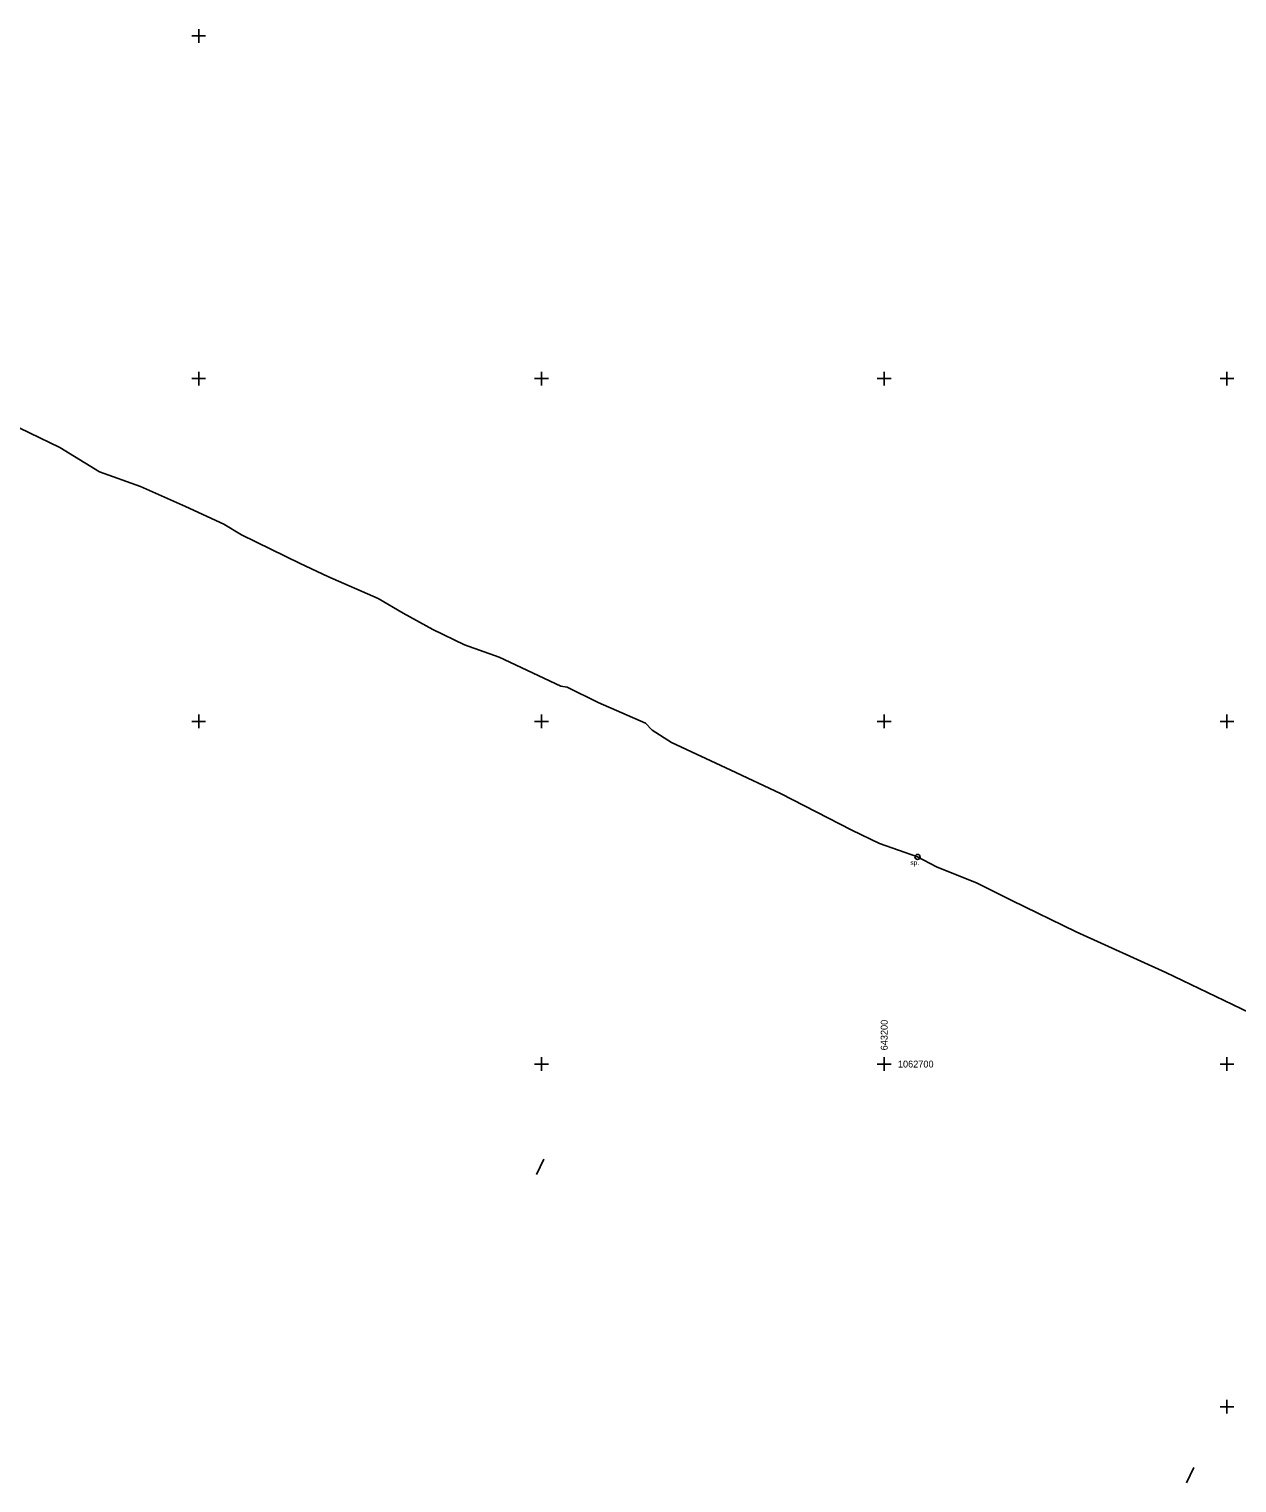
# Model space of a CAD drawing. Extents: x -643802 to -640936, y -1063811 to -1062198.
# Drawn here: x -643449.5 to -643097.1, y -1062822.2 to -1062398 of the extents above; entities that cross this region are included whole.
import ezdxf

# ---------------------------------------------------------------- set-up
doc = ezdxf.new("R2010")
doc.units = 0
for name, color, linetype in [('Vrstva 60', 7, 'Continuous'), ('Vrstva 8', 7, 'Continuous'), ('Vrstva 9', 7, 'Continuous')]:
    doc.layers.add(name, color=color, linetype=linetype)

msp = doc.modelspace()

# ---------------------------------------------------------------- linework, layer by layer
at = {"layer": 'Vrstva 60'}
for points in [[(-643398, -1062400), (-643402, -1062400)], [(-643400, -1062398), (-643400, -1062402)], [(-643400, -1062498), (-643400, -1062502)], [(-643300, -1062498), (-643300, -1062502)], [(-643200, -1062498), (-643200, -1062502)], [(-643100, -1062498), (-643100, -1062502)], [(-643398, -1062500), (-643402, -1062500)], [(-643298, -1062500), (-643302, -1062500)], [(-643198, -1062500), (-643202, -1062500)], [(-643098, -1062500), (-643102, -1062500)], [(-643398, -1062600), (-643402, -1062600)], [(-643400, -1062598), (-643400, -1062602)], [(-643298, -1062600), (-643302, -1062600)], [(-643300, -1062598), (-643300, -1062602)], [(-643198, -1062600), (-643202, -1062600)], [(-643200, -1062598), (-643200, -1062602)], [(-643098, -1062600), (-643102, -1062600)], [(-643100, -1062598), (-643100, -1062602)], [(-643298, -1062700), (-643302, -1062700)], [(-643300, -1062698), (-643300, -1062702)], [(-643198, -1062700), (-643202, -1062700)], [(-643200, -1062698), (-643200, -1062702)], [(-643098, -1062700), (-643102, -1062700)], [(-643100, -1062698), (-643100, -1062702)], [(-643301.484, -1062732.21), (-643299.366, -1062727.745)], [(-643100, -1062798), (-643100, -1062802)], [(-643098, -1062800), (-643102, -1062800)], [(-643111.748, -1062822.212), (-643109.63, -1062817.747)]]:
    msp.add_lwpolyline(points, dxfattribs=at)
at = {"layer": 'Vrstva 8'}
msp.add_lwpolyline([(-643467.19, -1062507.22), (-643440.51, -1062520.07), (-643428.95, -1062527.23), (-643417, -1062531.48), (-643403.89, -1062537.31), (-643392.67, -1062542.44), (-643387.58, -1062545.57), (-643370.39, -1062553.92), (-643362.37, -1062557.69), (-643347.63, -1062564.19), (-643340.35, -1062568.39), (-643331.75, -1062573.17), (-643322.48, -1062577.71), (-643312.32, -1062581.29), (-643294.34, -1062589.7), (-643292.5, -1062589.99), (-643283.44, -1062594.47), (-643269.69, -1062600.53), (-643267.69, -1062602.55), (-643262.1, -1062606.13), (-643244.77, -1062614.28), (-643230.28, -1062621.06), (-643209.47, -1062631.73), (-643201.41, -1062635.63), (-643190.27, -1062639.55), (-643184.75, -1062642.47), (-643172.87, -1062647.22), (-643162.78, -1062652.25), (-643143.97, -1062661.4), (-643117.8, -1062673.27), (-643098.33, -1062682.65), (-643085.98, -1062688.5)], dxfattribs=at)
msp.add_circle((-643190.27, -1062639.55), 0.75, dxfattribs=at)

# ---------------------------------------------------------------- texts
at = {"layer": 'Vrstva 60'}
msp.add_text('643200', height=2, rotation=90, dxfattribs=at).set_placement((-643199, -1062696))
msp.add_text('1062700', height=2, dxfattribs=at).set_placement((-643196, -1062701))
at = {"layer": 'Vrstva 9'}
msp.add_text('sp.', height=1.4, dxfattribs=at).set_placement((-643192.356, -1062641.93))

doc.saveas('drawing.dxf')
